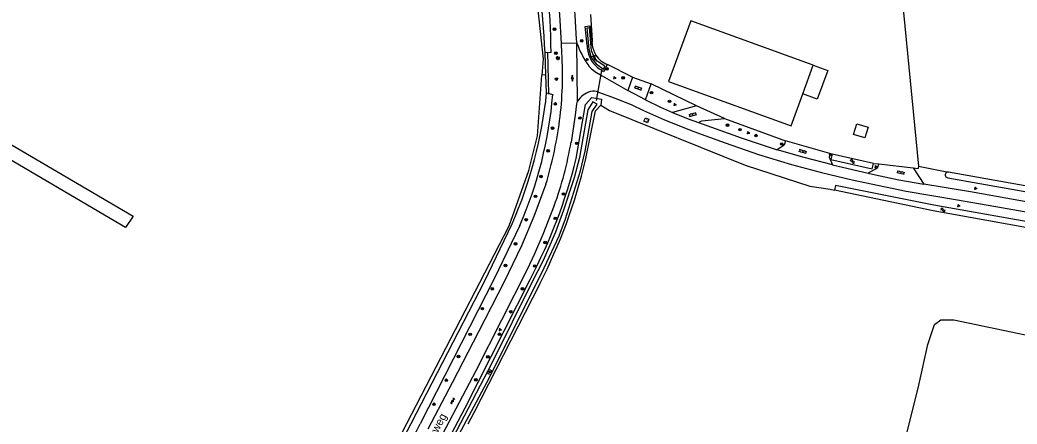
# Model space of a CAD drawing. Extents: x 124000 to 129000, y 395500 to 397503.
# Drawn here: x 125816.2 to 126127.7, y 396837.7 to 396964.1 of the extents above; entities that cross this region are included whole.
import ezdxf

# ---------------------------------------------------------------- set-up
doc = ezdxf.new("R2010")
doc.units = 0
for name, color, linetype in [('gg-afsc-draadraster', 7, 'Continuous'), ('gg-afsc-hekwerk', 7, 'Continuous'), ('gg-anno-openbare ruimte label', 7, 'Continuous'), ('gg-bbg-bijgebouw', 7, 'Continuous'), ('gg-bbg-hoofdgebouw', 7, 'Continuous'), ('gg-bbg-luifel en loopbrug', 7, 'Continuous'), ('gg-knt-bronhoudergrens', 7, 'Continuous'), ('gg-knt-verharding', 7, 'Continuous'), ('gg-kntw-bovenkant insteek waterloop', 7, 'Continuous'), ('gg-kntw-waterlijn', 7, 'Continuous'), ('gg-kwrk-duiker nz buis', 7, 'Continuous'), ('gt-grn-groengrens', 7, 'Continuous'), ('gt-grn-vlakafsluiter', 7, 'Continuous'), ('gt-grn-weggrens', 7, 'Continuous'), ('gt-symb-boom', 7, 'Continuous'), ('gt-symb-gesloten verharding', 7, 'Continuous'), ('gt-symb-groenvak', 7, 'Continuous'), ('gt-symb-klinker verharding', 7, 'Continuous'), ('gt-symb-lichtmast', 7, 'Continuous'), ('gt-symb-nortonput', 7, 'Continuous'), ('gt-symb-watersymbool', 7, 'Continuous'), ('gx-grn-maaiveld', 7, 'Continuous')]:
    doc.layers.add(name, color=color, linetype=linetype)

# ---------------------------------------------------------------- blocks, each defined once
blk = doc.blocks.new('gt0-BOOM')
at = {"layer": 'gt-symb-boom'}
for radius in [0.4, 0.2]:
    blk.add_circle((0, 0), radius, dxfattribs=at)
blk = doc.blocks.new('gt0-GRVAK')
at = {"layer": 'gt-symb-groenvak'}
for p, q in [((-0.11, 0.19), (-0.23, 0.24)), ((-0.18, 0.15), (0.09, 0.15)), ((-0.09, 0.21), (-0.16, 0.32)), ((-0.05, 0.21), (-0.05, 0.39)), ((0, 0.21), (0.06, 0.32)), ((0.01, 0.19), (0.13, 0.24)), ((0.26, -0.05), (0.2, 0.06)), ((0.3, -0.05), (0.3, 0.13)), ((0.35, -0.05), (0.41, 0.06)), ((-0.25, -0.23), (-0.36, -0.18)), ((-0.32, -0.26), (-0.05, -0.26)), ((-0.23, -0.21), (-0.29, -0.09)), ((-0.18, -0.2), (-0.18, -0.02)), ((-0.14, -0.21), (-0.07, -0.09)), ((-0.12, -0.23), (0, -0.18)), ((0.24, -0.07), (0.12, -0.02)), ((0.17, -0.11), (0.44, -0.11)), ((0.37, -0.07), (0.49, -0.02))]:
    blk.add_line(p, q, dxfattribs=at)
blk = doc.blocks.new('gt0-KL1')
at = {"layer": 'gt-symb-klinker verharding'}
for p, q in [((-1.15, 0.3), (1.15, 0.3)), ((-1, -0.3), (-1, 0.3)), ((-0.5, 0.3), (-0.5, 0.45)), ((0, -0.3), (0, 0.3)), ((0.5, 0.3), (0.5, 0.45)), ((1, -0.3), (1, 0.3)), ((-1.15, -0.3), (1.15, -0.3)), ((-0.5, -0.45), (-0.5, -0.3)), ((0.5, -0.45), (0.5, -0.3))]:
    blk.add_line(p, q, dxfattribs=at)
blk = doc.blocks.new('gt0-NPUT')
at = {"layer": 'gt-symb-nortonput'}
blk.add_lwpolyline([(-0.57, -0.61), (-0.57, 0.59), (0.63, 0.59), (0.63, -0.61)], close=True, dxfattribs=at)
blk.add_text('N', height=0.7, dxfattribs=at).set_placement((-0.22, -0.38))
blk = doc.blocks.new('gt0-GESVH1')
at = {"layer": 'gt-symb-gesloten verharding'}
for p, q in [((-0.99, -0.26), (0.01, 0.24)), ((0.01, -0.26), (-0.99, 0.24)), ((0.01, 0.24), (1.01, -0.26)), ((1.01, 0.24), (0.01, -0.26))]:
    blk.add_line(p, q, dxfattribs=at)
blk = doc.blocks.new('gt0-WA')
at = {"layer": 'gt-symb-watersymbool'}
for centre, start, end in [((-0.32, 0.02), 28.0725, 151.9275), ((0.43, 0.42), 208.0725, 331.9275), ((-0.32, -0.43), 28.0725, 151.9275), ((0.43, -0.03), 208.0725, 331.9275)]:
    blk.add_arc(centre, 0.425, start, end, dxfattribs=at)
blk = doc.blocks.new('gt0-LMAST')
at = {"layer": 'gt-symb-lichtmast'}
for p, q in [((-0.18, 0.17), (-0.45, 0.44)), ((-0.01, 0.25), (-0.01, 0.62)), ((0.17, 0.17), (0.44, 0.44)), ((-0.26, 0), (-0.63, 0)), ((-0.18, -0.18), (-0.45, -0.45)), ((-0.01, -0.25), (-0.01, -0.63)), ((0.44, -0.45), (0.17, -0.18)), ((0.24, 0), (0.62, 0))]:
    blk.add_line(p, q, dxfattribs=at)
blk.add_circle((-0.01, 0), 0.25, dxfattribs=at)

msp = doc.modelspace()

# ---------------------------------------------------------------- linework, layer by layer
at = {"layer": 'gg-afsc-draadraster'}
msp.add_line((126096.9, 396918.38), (126106.26, 396916.48), dxfattribs=at)
msp.add_lwpolyline([(125985.89, 397035.02), (126088.08, 397023.27), (126092.18, 396966.39), (126096.9, 396918.38)], dxfattribs=at)
at = {"layer": 'gg-afsc-hekwerk'}
msp.add_line((126007.59, 396946.21), (126013.43, 396944.1), dxfattribs=at)
at = {"layer": 'gg-bbg-bijgebouw'}
for p, q in [((126060.79, 396940.98), (126064.04, 396949.91)), ((126057.13, 396930.94), (126060.79, 396940.98))]:
    msp.add_line(p, q, dxfattribs=at)
msp.add_lwpolyline([(126064.04, 396949.91), (126025.75, 396963.83), (126018.85, 396944.87), (126057.13, 396930.94)], dxfattribs=at)
at = {"layer": 'gg-bbg-hoofdgebouw'}
msp.add_lwpolyline([(126076.62, 396928.25), (126077.67, 396931.58), (126081.14, 396930.5), (126080.11, 396927.16), (126076.62, 396928.25)], dxfattribs=at)
at = {"layer": 'gg-bbg-luifel en loopbrug'}
msp.add_lwpolyline([(126064.04, 396949.91), (126068.55, 396948.27), (126065.31, 396939.34), (126060.79, 396940.98)], dxfattribs=at)
at = {"layer": 'gg-knt-bronhoudergrens'}
msp.add_line((126042.77, 396918.68), (126062.94, 396912.13), dxfattribs=at)
for points in [[(125997.73, 396937.46), (126000.34, 396935.75), (126042.77, 396918.68)], [(126062.94, 396912.13), (126069.29, 396911.1), (126070.65, 396910.81)], [(126075.95, 396765.91), (126075.95, 396768.17), (126078.86, 396778.16), (126088.41, 396815.13), (126097.05, 396849.81), (126099.87, 396862.59), (126101.86, 396868.84), (126103.89, 396870.28), (126107.98, 396870.26), (126149.75, 396861.53), (126187.35, 396853.68), (126187.5, 396853.06)]]:
    msp.add_lwpolyline(points, dxfattribs=at)
at = {"layer": 'gg-knt-verharding'}
for p, q in [((125985.51, 396953.73), (125985.35, 396956.75)), ((126007.59, 396946.21), (126006.07, 396942.02)), ((126011.64, 396939.13), (126006.07, 396942.02)), ((126011.64, 396939.13), (126013.43, 396944.1)), ((126027.6, 396937.2), (126020.11, 396935.1)), ((126028.22, 396931.97), (126029.23, 396932.51)), ((126029.23, 396932.51), (126036.29, 396933.24)), ((126036.29, 396933.24), (126055.41, 396926.23)), ((126055.41, 396926.23), (126054.91, 396924.89)), ((126054.91, 396924.89), (126052.72, 396923.49)), ((126069.26, 396922.33), (126068.97, 396921.12)), ((126068.97, 396921.12), (126070.07, 396918.73)), ((126070.07, 396918.73), (126081.17, 396916.13)), ((126084.26, 396917.79), (126081.17, 396916.13)), ((126084.26, 396917.79), (126084.55, 396919.03)), ((126095.25, 396917.84), (126098.59, 396912.72))]:
    msp.add_line(p, q, dxfattribs=at)
for points in [[(125953.66, 397222.26), (125956.2, 397204.11), (125960.71, 397172.66), (125965.33, 397140.9), (125970.02, 397108.97), (125973.96, 397081.84), (125980.47, 397036.3), (125980.87, 397035.48), (125981.57, 397030.88), (125981.45, 397030.07), (125983.5, 397015.58), (125986, 396997.02), (125987.62, 396984.74), (125988.09, 396980.94), (125989.12, 396970.72), (125989.51, 396965.6), (125989.93, 396957.97), (125990.04, 396957.38), (125990.2, 396956.8)], [(125985.35, 396956.75), (125984.88, 396965.71), (125984.4, 396971.76), (125983.71, 396978.72), (125982.75, 396986.62), (125980.84, 397001.34), (125978.58, 397017.61), (125976.01, 397035.11), (125966, 397104.57), (125961.33, 397136.24), (125957.33, 397163.9), (125954.44, 397184.02), (125952.28, 397199.63), (125951.13, 397208.1), (125949.87, 397217.9)], [(125993.88, 396949.72), (125994.68, 396948.86), (125995.85, 396947.92), (125998.1, 396946.56), (126006.07, 396942.02)], [(125996.99, 396941.52), (126000.98, 396940.07), (126007.16, 396937.62), (126011, 396935.8), (126017.55, 396932.78), (126026.74, 396929.2), (126036.51, 396925.61), (126046.93, 396922), (126057.21, 396918.9), (126066.65, 396916.39), (126076.19, 396914.06), (126086.58, 396911.83), (126093.08, 396910.57), (126109.07, 396907.79), (126122.8, 396905.46), (126136.99, 396902.91), (126140.39, 396902.28)], [(125990.38, 396938.66), (125990.2, 396938.24), (125990.1, 396937.82), (125989.63, 396934.32), (125988.38, 396925.85)], [(126011.64, 396939.13), (126016.33, 396936.82), (126020.11, 396935.1)], [(126020.11, 396935.1), (126025, 396933.14), (126028.22, 396931.97)], [(126028.22, 396931.97), (126041.56, 396927.16), (126052.72, 396923.49)], [(126070.07, 396918.73), (126061.15, 396921), (126052.72, 396923.49)], [(126081.17, 396916.13), (126083.47, 396915.59), (126090.76, 396914.08), (126098.59, 396912.72)], [(125980.51, 396912.67), (125976.73, 396902.63), (125972.88, 396893.38), (125967.45, 396882.19), (125959.5, 396866.51), (125951.27, 396850.56), (125943.64, 396836.08)], [(126141.38, 396905.29), (126128.27, 396907.65), (126113.12, 396910.28), (126098.59, 396912.72)], [(125983.13, 396905.99), (125979.55, 396896.93), (125976.99, 396890.93), (125974.62, 396886), (125966.68, 396870.14), (125958.6, 396854.36), (125950.26, 396838.46), (125942.5, 396823.73), (125934.27, 396808.37), (125927.43, 396796.12), (125920.49, 396783.75), (125920.28, 396783.05)]]:
    msp.add_lwpolyline(points, dxfattribs=at)
for centre, radius, start, end in [((126018.39, 396966.94), 29.95, 199.7956, 215.0895), ((125874.5, 396946.82), 111.22, 352.6458, 3.5628), ((125997.04, 396934.03), 8.12, 108.6651, 145.1919), ((125995.37, 396937.24), 4.58, 69.3907, 101.6911), ((125858, 396949.55), 127.94, 343.246, 352.3763), ((125879.98, 396943.87), 109.89, 339.8312, 350.5596)]:
    msp.add_arc(centre, radius, start, end, dxfattribs=at)
at = {"layer": 'gg-kntw-bovenkant insteek waterloop'}
for p, q in [((125982.15, 396953.85), (125980.27, 396953.8)), ((125998.57, 396947.97), (125999.78, 396950.17)), ((125980.74, 396941.32), (125982.66, 396940.73)), ((126082.88, 396919.22), (126069.96, 396922.13))]:
    msp.add_line(p, q, dxfattribs=at)
for points in [[(125993.4, 396956.23), (125992.78, 396962.01), (125994.29, 396962.24), (125995.01, 396956.37)], [(125989.95, 396920.71), (125992.93, 396937.59), (125994.9, 396939.84), (125997.92, 396939.28), (125997.73, 396937.46)], [(125992.92, 396920.18), (125996.04, 396935.67), (125997.73, 396937.46)], [(126069.96, 396922.13), (126069.57, 396920.39), (126082.49, 396917.48), (126082.88, 396919.22)], [(126176.74, 396903.52), (126140.15, 396910.46), (126106.26, 396916.48)], [(126106.06, 396914.74), (126150.76, 396906.79), (126166.78, 396903.69), (126176.38, 396901.63), (126176.74, 396903.52)], [(126182.01, 396889.02), (126182.47, 396890.73), (126153.3, 396896.92), (126101.74, 396906.15), (126070.99, 396912.3), (126070.65, 396910.81)], [(126182.01, 396889.02), (126152.91, 396895.08), (126101.51, 396904.33), (126070.65, 396910.81)], [(125938.42, 396837.9), (125961.37, 396882.29), (125969.96, 396900.3)], [(125972.38, 396899.81), (125964.4, 396883.08), (125941.26, 396837.74)], [(125925.7, 396780.95), (125922.98, 396782.39), (125935.85, 396805.65), (125955.26, 396842.78), (125975.59, 396882.94)], [(125978.63, 396881.54), (125958.05, 396841.21), (125956.12, 396837.62)]]:
    msp.add_lwpolyline(points, dxfattribs=at)
for centre, radius, start, end in [((125529.3, 396930.1), 451.59, 3.0088, 8.3083), ((125681.13, 396949.46), 301.05, 0.8349, 8.6052), ((126002.43, 396956.13), 9.03, 179.3398, 204.415), ((126002.08, 396956.88), 7.09, 184.0884, 212.16), ((126002.43, 396956.13), 9.03, 204.4565, 244.656), ((126002.08, 396956.88), 7.09, 212.1861, 251.0853), ((125846.42, 396954.71), 134.99, 336.2342, 354.3106), ((125853.62, 396951.38), 129.48, 336.526, 355.2817), ((125832.2, 396959.11), 162.36, 332.0218, 346.3191), ((125822.49, 396961.24), 175.3, 332.9591, 346.4558), ((126106.13, 396915.61), 0.873, 81.0443, 265.9851), ((124676.17, 397501.47), 1426.04, 329.03547, 332.2685), ((124856.93, 397397.59), 1220.32, 328.85494, 332.69204)]:
    msp.add_arc(centre, radius, start, end, dxfattribs=at)
at = {"layer": 'gg-kntw-waterlijn'}
for points in [[(125994.68, 396952.57), (125994.05, 396954.82), (125993.39, 396961.62), (125993.99, 396961.68), (125994.68, 396954.5), (125995.42, 396952.85)], [(125994.68, 396952.57), (125994.98, 396951.9), (125996.19, 396950.37), (125998.47, 396948.69), (125998.98, 396949.63), (125996.55, 396951.19), (125995.42, 396952.85)], [(125995.14, 396938.45), (125993.58, 396935.93), (125991.02, 396921.01), (125989.34, 396914.74), (125986.06, 396904.57), (125983.53, 396897.74), (125979.71, 396888.82), (125976.31, 396882.35), (125963.64, 396856.68), (125940.36, 396812.03), (125923.99, 396782.52), (125925.12, 396781.89), (125931.91, 396794.14), (125962.06, 396850.73), (125979.3, 396884.97), (125984.71, 396896.53), (125986.64, 396901.86), (125991.36, 396916.87), (125992.75, 396923.04), (125994.96, 396935.49), (125996.55, 396937.78), (125995.14, 396938.45)]]:
    msp.add_lwpolyline(points, dxfattribs=at)
at = {"layer": 'gg-kwrk-duiker nz buis'}
for p, q in [((125981.48, 396940.86), (125981.13, 396953.98)), ((125996.3, 396938.92), (125998.11, 396948.84))]:
    msp.add_line(p, q, dxfattribs=at)
at = {"layer": 'gt-grn-groengrens'}
for p, q in [((125980.53, 396946.89), (125980.27, 396953.8)), ((126007.59, 396946.21), (125999.78, 396950.17)), ((125980.53, 396946.89), (125979.3, 396946.81)), ((125980.74, 396941.32), (125980.53, 396946.89)), ((126027.6, 396937.2), (126013.43, 396944.1)), ((126069.96, 396922.13), (126069.26, 396922.33)), ((126082.88, 396919.22), (126084.55, 396919.03)), ((126095.25, 396917.84), (126096.81, 396917.66)), ((126096.9, 396918.38), (126096.81, 396917.66))]:
    msp.add_line(p, q, dxfattribs=at)
for points in [[(125975.04, 397000), (125975.91, 396992.61), (125976.83, 396977.85), (125979.68, 396951.8), (125979.3, 396946.81)], [(125995.01, 396956.37), (125995.09, 396957.67), (125994.56, 396965.78)], [(125869.01, 396719.7), (125869, 396719.71), (125876.35, 396731.99), (125902.97, 396776.26), (125932.54, 396829.04), (125969.1, 396899.65), (125975.16, 396917.03), (125977.91, 396927.8), (125979.3, 396946.81)]]:
    msp.add_lwpolyline(points, dxfattribs=at)
at = {"layer": 'gt-grn-vlakafsluiter'}
for p, q in [((125994.21, 396952.39), (125994.68, 396952.57)), ((125994.68, 396952.57), (125995.42, 396952.85)), ((125995.42, 396952.85), (125996.08, 396953.1)), ((126036.29, 396933.24), (126027.6, 396937.2)), ((126069.26, 396922.33), (126055.41, 396926.23)), ((126084.55, 396919.03), (126095.25, 396917.84))]:
    msp.add_line(p, q, dxfattribs=at)
at = {"layer": 'gt-grn-weggrens'}
for p, q in [((125990.2, 396956.8), (125985.35, 396956.75)), ((125990.38, 396938.66), (125990.2, 396956.8))]:
    msp.add_line(p, q, dxfattribs=at)
at = {"layer": 'gx-grn-maaiveld'}
msp.add_lwpolyline([(125583.72, 397061.83), (125586.12, 397058.49), (125590.62, 397054.52), (125731.34, 396972.73), (125734.29, 396973.16), (125739.68, 396969.29), (125747.86, 396963.98), (125766.29, 396952.77), (125851.61, 396902.73), (125849.2, 396899.13), (125736.37, 396965.58), (125723.44, 396972.89), (125652.98, 397014.22), (125582.31, 397055.4), (125575.26, 397057.95), (125562.45, 397063.6), (125549.07, 397071.71), (125532.3, 397083.76), (125522.12, 397090.34), (125513.32, 397095.54), (125505.18, 397099.05), (125501.91, 397100.01), (125489.35, 397102.15)], dxfattribs=at)

# ---------------------------------------------------------------- block references
at = {"layer": 'gt-symb-boom'}
for p in [(125983.23, 396961.18), (125991.71, 396957.53), (125983.66, 396953.69), (125999.58, 396948.78), (125983.81, 396945.58), (126004.67, 396945.97), (126013.52, 396941.33), (125983.47, 396937.81), (126019.11, 396938.61), (125991.15, 396933.42), (125982.62, 396930.21), (126037.27, 396931.15), (126041.16, 396929.77), (125990.12, 396925.49), (126046.16, 396927.91), (126054.19, 396925.28), (125981.2, 396923.13), (126069.47, 396921.94), (125978.99, 396915.09), (125977.28, 396908.89), (125985.99, 396909.63), (125974.35, 396901.59), (125983.45, 396902.04), (125980.26, 396894.49), (125971.03, 396894.05), (125967.89, 396887.26), (125977.01, 396887.13), (125963.78, 396879.98), (125973.2, 396879.99), (125960.68, 396873.78), (125969.54, 396872.81), (125956.85, 396865.74), (125966.02, 396865.77), (125953.22, 396858.81), (125962.37, 396858.71), (125949.42, 396851.39), (125958.63, 396851.52), (125945.57, 396843.88)]:
    msp.add_blockref('gt0-BOOM', p, dxfattribs=at)
at = {"layer": 'gt-symb-gesloten verharding'}
for p, rotation in [((125988.77, 396945.84), 93.2116257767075), ((125951.35, 396844.88), 62.99934529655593)]:
    msp.add_blockref('gt0-GESVH1', p, dxfattribs=dict(at, rotation=rotation))
at = {"layer": 'gt-symb-groenvak'}
for p in [(125993.39, 396951.74), (126001.96, 396945.99), (126020.78, 396937.63), (126043.69, 396928.82), (126083.62, 396918.2), (126114.74, 396911.43), (126109.42, 396906), (125966.22, 396867.24)]:
    msp.add_blockref('gt0-GRVAK', p, dxfattribs=at)
at = {"layer": 'gt-symb-klinker verharding'}
for p, rotation in [((126009.33, 396942.79), -19.684642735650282), ((126026.43, 396934.48), 15.787947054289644), ((126060.76, 396922.9), 163.6136943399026), ((126091.41, 396916.36), -12.702731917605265)]:
    msp.add_blockref('gt0-KL1', p, dxfattribs=dict(at, rotation=rotation))
at = {"layer": 'gt-symb-lichtmast'}
msp.add_blockref('gt0-LMAST', (125984.3, 396952.14), dxfattribs=at)
at = {"layer": 'gt-symb-nortonput', "rotation": -24.154560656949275}
msp.add_blockref('gt0-NPUT', (126011.89, 396932.72), dxfattribs=at)
at = {"layer": 'gt-symb-watersymbool'}
for p, rotation in [((125995.69, 396952.07), -57.99461679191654), ((126076.23, 396919.85), -21.04574081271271), ((126104.49, 396904.66), -10.36632260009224), ((125962.92, 396853.96), 62.40963046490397)]:
    msp.add_blockref('gt0-WA', p, dxfattribs=dict(at, rotation=rotation))

# ---------------------------------------------------------------- texts
at = {"layer": 'gg-anno-openbare ruimte label'}
msp.add_text('Hultenseweg', height=2.5, rotation=62.1, dxfattribs=at).set_placement((125940.57, 396823.15))

doc.saveas('drawing.dxf')
